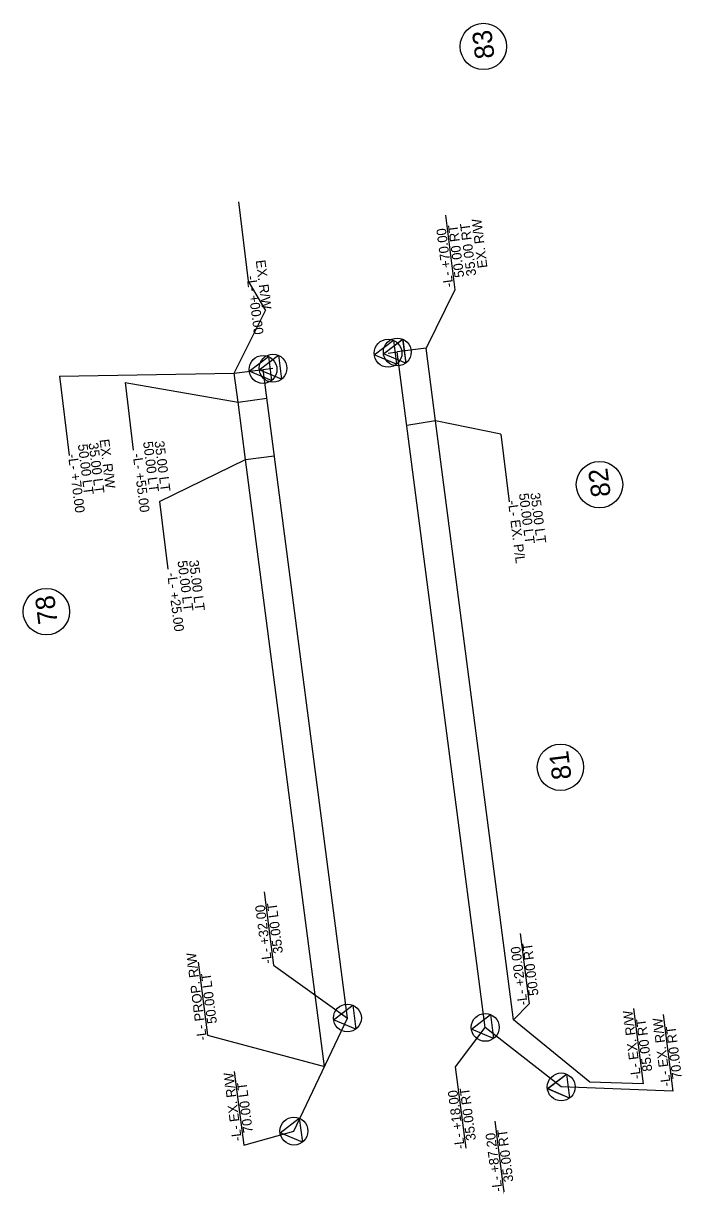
# Model space of a CAD drawing. Extents: x 2368169 to 2369183, y 801414 to 808542.
# Drawn here: x 2368169 to 2368509, y 807942 to 808542 of the extents above; entities that cross this region are included whole.
import ezdxf

# ---------------------------------------------------------------- set-up
doc = ezdxf.new("R2010")
doc.units = 0
for name, color, linetype in [('Prop Easement Construction', 7, 'Continuous'), ('Prop Easement Construction Station Offsets', 7, 'Continuous'), ('Prop Easement Permanent Drainage Utility', 7, 'Continuous'), ('Prop Easement Permanent Drainage Utility Station Offsets', 7, 'Continuous'), ('Prop Easement Permanent Utility', 7, 'Continuous'), ('Prop Easement Permanent Utility Station Offsets', 7, 'Continuous'), ('Prop Parcel Number CELL', 7, 'Continuous'), ('Prop Parcel Number Text', 7, 'Continuous'), ('Prop ROW Marker CELL', 7, 'Continuous'), ('Prop ROW RW Lines', 7, 'Continuous'), ('Prop ROW Station Offsets', 7, 'Continuous')]:
    doc.layers.add(name, color=color, linetype=linetype)

msp = doc.modelspace()

# ---------------------------------------------------------------- linework, layer by layer
at = {"layer": 'Prop Easement Construction'}
msp.add_line((2368277.78, 808360.8), (2368293.85, 808393.15), dxfattribs=at)
at = {"layer": 'Prop Easement Construction Station Offsets'}
msp.add_lwpolyline([(2368279.96, 808449.44), (2368284.96, 808408.34), (2368293.85, 808393.15)], dxfattribs=at)
at = {"layer": 'Prop Easement Permanent Drainage Utility'}
for p, q in [((2368376.94, 808373.72), (2368362.07, 808371.78)), ((2368381.83, 808336.21), (2368376.94, 808373.72)), ((2368279.72, 808345.93), (2368294.59, 808347.87)), ((2368283.59, 808316.18), (2368279.72, 808345.93)), ((2368283.59, 808316.18), (2368298.46, 808318.12))]:
    msp.add_line(p, q, dxfattribs=at)
at = {"layer": 'Prop Easement Permanent Drainage Utility Station Offsets'}
for p, q in [((2368386.97, 808442.43), (2368391.89, 808403.93)), ((2368391.89, 808403.93), (2368376.94, 808373.72)), ((2368221.29, 808356.07), (2368225.54, 808321.12)), ((2368221.29, 808356.07), (2368279.72, 808345.93)), ((2368239.09, 808294.47), (2368283.59, 808316.18)), ((2368239.09, 808294.47), (2368243.34, 808259.52))]:
    msp.add_line(p, q, dxfattribs=at)
at = {"layer": 'Prop Easement Permanent Utility'}
for p, q in [((2368277.78, 808360.8), (2368292.66, 808362.74)), ((2368279.72, 808345.93), (2368277.78, 808360.8)), ((2368381.83, 808336.21), (2368367.01, 808333.81)), ((2368422.13, 808026.65), (2368381.83, 808336.21)), ((2368324.43, 808002.53), (2368283.59, 808316.18)), ((2368461.63, 807994.38), (2368422.13, 808026.65))]:
    msp.add_line(p, q, dxfattribs=at)
at = {"layer": 'Prop Easement Permanent Utility Station Offsets'}
for p, q in [((2368415.62, 808329.28), (2368381.83, 808336.21)), ((2368415.62, 808329.28), (2368419.87, 808294.33)), ((2368425.63, 808071.3), (2368430.29, 808034.87)), ((2368430.29, 808034.87), (2368422.13, 808026.65))]:
    msp.add_line(p, q, dxfattribs=at)
for points in [[(2368259.14, 808056.47), (2368263.96, 808018.76), (2368324.43, 808002.53)], [(2368484.17, 808032.45), (2368489.13, 807993.6), (2368461.63, 807994.38)]]:
    msp.add_lwpolyline(points, dxfattribs=at)
at = {"layer": 'Prop Parcel Number CELL'}
for p, q in [((2368406.58, 808529.7), (2368406.58, 808529.7)), ((2368466.64, 808303.22), (2368466.64, 808303.22)), ((2368180.62, 808237.57), (2368180.62, 808237.57)), ((2368446.43, 808157.16), (2368446.43, 808157.16))]:
    msp.add_line(p, q, dxfattribs=at)
for centre in [(2368406.58, 808529.7), (2368466.64, 808303.22), (2368180.62, 808237.57), (2368446.43, 808157.16)]:
    msp.add_circle(centre, 12, dxfattribs=at)
at = {"layer": 'Prop ROW Marker CELL'}
for p, q in [((2368357.28, 808371.16), (2368357.28, 808371.16)), ((2368357.28, 808371.16), (2368357.28, 808371.16)), ((2368362.07, 808371.78), (2368362.07, 808371.78)), ((2368362.07, 808371.78), (2368362.07, 808371.78)), ((2368292.66, 808362.74), (2368292.66, 808362.74)), ((2368292.66, 808362.74), (2368292.66, 808362.74)), ((2368297.78, 808363.41), (2368297.78, 808363.41)), ((2368297.78, 808363.41), (2368297.78, 808363.41)), ((2368336.29, 808027.57), (2368336.29, 808027.57)), ((2368336.29, 808027.57), (2368336.29, 808027.57)), ((2368407.52, 808022.73), (2368407.52, 808022.73)), ((2368407.52, 808022.73), (2368407.52, 808022.73)), ((2368446.81, 807991.97), (2368446.81, 807991.97)), ((2368446.81, 807991.97), (2368446.81, 807991.97)), ((2368308.61, 807969.13), (2368308.61, 807969.13)), ((2368308.61, 807969.13), (2368308.61, 807969.13))]:
    msp.add_line(p, q, dxfattribs=at)
for points in [[(2368361.65, 808365.42), (2368350.14, 808370.24), (2368360.05, 808377.81)], [(2368361.64, 808365.41), (2368350.14, 808370.24), (2368360.06, 808377.81)], [(2368366.44, 808366.04), (2368354.93, 808370.86), (2368364.84, 808378.44)], [(2368366.43, 808366.04), (2368354.93, 808370.87), (2368364.85, 808378.43)], [(2368302.15, 808357.67), (2368290.64, 808362.49), (2368300.56, 808370.07)], [(2368302.15, 808357.67), (2368290.64, 808362.5), (2368300.56, 808370.07)], [(2368297.02, 808357), (2368285.51, 808361.82), (2368295.43, 808369.4)], [(2368297.02, 808357), (2368285.51, 808361.83), (2368295.43, 808369.4)], [(2368340.66, 808021.83), (2368329.15, 808026.65), (2368339.07, 808034.23)], [(2368340.66, 808021.83), (2368329.15, 808026.66), (2368339.07, 808034.23)], [(2368411.88, 808016.99), (2368400.37, 808021.8), (2368410.29, 808029.38)], [(2368411.88, 808016.98), (2368400.37, 808021.81), (2368410.29, 808029.38)], [(2368451.18, 807986.23), (2368439.67, 807991.05), (2368449.59, 807998.63)], [(2368451.18, 807986.23), (2368439.67, 807991.06), (2368449.59, 807998.63)], [(2368312.97, 807963.39), (2368301.46, 807968.22), (2368311.39, 807975.79)], [(2368312.98, 807963.4), (2368301.47, 807968.21), (2368311.38, 807975.79)]]:
    msp.add_lwpolyline(points, close=True, dxfattribs=at)
for centre in [(2368357.28, 808371.16), (2368362.07, 808371.78), (2368292.66, 808362.74), (2368297.78, 808363.41), (2368336.29, 808027.57), (2368407.52, 808022.73), (2368446.81, 807991.97), (2368308.61, 807969.13)]:
    msp.add_circle(centre, 7.2, dxfattribs=at)
at = {"layer": 'Prop ROW RW Lines'}
for p, q in [((2368357.28, 808371.16), (2368362.07, 808371.78)), ((2368407.52, 808022.73), (2368362.07, 808371.78)), ((2368292.66, 808362.74), (2368297.78, 808363.41)), ((2368336.29, 808027.57), (2368292.66, 808362.74)), ((2368308.61, 807969.13), (2368336.29, 808027.57)), ((2368446.81, 807991.97), (2368407.52, 808022.73))]:
    msp.add_line(p, q, dxfattribs=at)
at = {"layer": 'Prop ROW Station Offsets'}
for q in [(2368277.78, 808360.8), (2368192.42, 808318.27)]:
    msp.add_line((2368187.43, 808359.37), q, dxfattribs=at)
for points in [[(2368293.27, 808092.77), (2368298.1, 808054.89), (2368336.29, 808027.57)], [(2368499.51, 808029.45), (2368504.58, 807989.75), (2368446.81, 807991.97)], [(2368397.6, 807960.37), (2368392.24, 808002.36), (2368407.52, 808022.73)], [(2368277.77, 807999.91), (2368282.64, 807961.78), (2368308.61, 807969.13)], [(2368412.48, 807974.29), (2368416.84, 807940.11), (2368424.4, 807893.02)]]:
    msp.add_lwpolyline(points, dxfattribs=at)

# ---------------------------------------------------------------- texts
at = {"layer": 'Prop Easement Construction Station Offsets'}
for s, p in [('EX. R/W', (2368288.85, 808419.05)), ('-L- +00.00', (2368284.12, 808410.91))]:
    msp.add_text(s, height=5, rotation=277.27835, dxfattribs=at).set_placement(p)
at = {"layer": 'Prop Easement Permanent Drainage Utility Station Offsets'}
for s, rotation, p in [('-L- +70.00', 97.27835, (2368391.05, 808405.56)), ('50.00 RT', 97.27835, (2368396.71, 808410.56)), ('35.00 RT', 97.27835, (2368402.91, 808411.35)), ('EX. R/W', 97.27835, (2368408.69, 808415.45)), ('50.00 LT', 277.27835, (2368230.59, 808325.3)), ('35.00 LT', 277.27835, (2368236.51, 808325.56)), ('-L- +55.00', 277.27835, (2368225.23, 808319.04)), ('50.00 LT', 277.27835, (2368248.39, 808263.7)), ('35.00 LT', 277.27835, (2368254.31, 808263.96)), ('-L- +25.00', 277.27835, (2368243.03, 808257.45))]:
    msp.add_text(s, height=5, rotation=rotation, dxfattribs=at).set_placement(p)
at = {"layer": 'Prop Easement Permanent Utility Station Offsets'}
for s, rotation, p in [('50.00 LT', 277.27835, (2368424.93, 808298.51)), ('35.00 LT', 277.27835, (2368430.84, 808298.78)), ('-L- EX. P/L', 277.27835, (2368419.25, 808294.76)), ('-L- +20.00', 97.27835, (2368429.46, 808034.39)), ('50.00 RT', 97.27835, (2368435.12, 808039.39)), ('-L- PROP. R/W', 97.27835, (2368263.65, 808016.26)), ('50.00 LT', 97.27835, (2368268.84, 808024.94)), ('-L- EX. R/W', 97.27835, (2368488.14, 807996.33)), ('85.00 RT', 97.27835, (2368493.95, 808000.21))]:
    msp.add_text(s, height=5, rotation=rotation, dxfattribs=at).set_placement(p)
at = {"layer": 'Prop Parcel Number Text'}
for s, p in [('83', (2368412.41, 808523.89)), ('82', (2368472.47, 808297.41)), ('78', (2368186.45, 808231.74)), ('81', (2368452.2, 808151.35))]:
    msp.add_text(s, height=10, rotation=97.10628, dxfattribs=at).set_placement(p)
at = {"layer": 'Prop ROW Station Offsets'}
for s, rotation, p in [('50.00 LT', 277.27835, (2368196.86, 808323.91)), ('35.00 LT', 277.27835, (2368202.39, 808324.62)), ('EX. R/W', 277.27835, (2368208.09, 808326.45)), ('-L- +70.00', 277.27835, (2368191.75, 808318.78)), ('-L- +32.00', 97.27835, (2368297.34, 808055.9)), ('35.00 LT', 97.27835, (2368302.97, 808061.19)), ('-L- EX. R/W', 97.27835, (2368503.52, 807992.49)), ('70.00 RT', 97.27835, (2368509.33, 807996.37)), ('-L- EX. R/W', 97.27835, (2368281.69, 807964.27)), ('70.00 LT', 97.27835, (2368287.46, 807968.45)), ('-L- +18.00', 97.27835, (2368397, 807960.15)), ('35.00 RT', 97.27835, (2368402.74, 807964.55)), ('-L- +87.20', 97.27835, (2368416.47, 807938.08)), ('35.00 RT', 97.27835, (2368422.14, 807943.08))]:
    msp.add_text(s, height=5, rotation=rotation, dxfattribs=at).set_placement(p)

doc.saveas('drawing.dxf')
